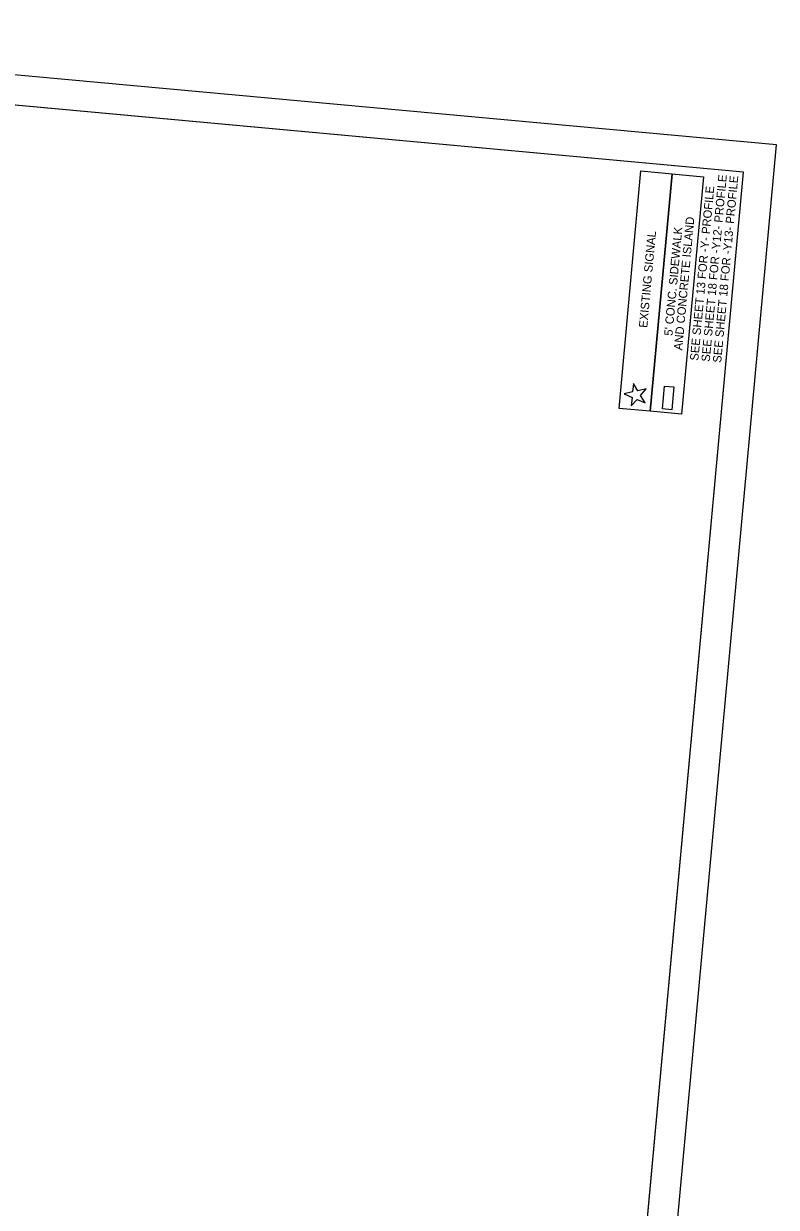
# Model space of a CAD drawing. Extents: x 2012234 to 2013485, y 445879 to 447846.
# Drawn here: x 2012860 to 2013485, y 446862 to 447846 of the extents above; entities that cross this region are included whole.
import ezdxf

# ---------------------------------------------------------------- set-up
doc = ezdxf.new("R2010")
doc.units = 0
for name, color, linetype in [('Old_Level_1', 7, 'Continuous'), ('Prop DSN Text', 7, 'Continuous'), ('Prop RDY Traffic Signal CELL', 7, 'Continuous'), ('Prop Shade Medium', 7, 'Continuous'), ('Sheet Clip Boundary CELL', 7, 'Continuous'), ('Sheet Plan And Profile CELL', 7, 'Continuous'), ('Sheet Plot Border Outside CELL', 7, 'Continuous')]:
    doc.layers.add(name, color=color, linetype=linetype)

msp = doc.modelspace()

# ---------------------------------------------------------------- linework, layer by layer
at = {"layer": 'Old_Level_1'}
for points in [[(2013354.62, 447526.24), (2013372.77, 447723.6), (2013398.72, 447721.22), (2013380.57, 447523.86)], [(2013380.57, 447523.86), (2013398.72, 447721.22), (2013424.67, 447718.83), (2013406.52, 447521.47)]]:
    msp.add_lwpolyline(points, close=True, dxfattribs=at)
at = {"layer": 'Prop RDY Traffic Signal CELL'}
msp.add_lwpolyline([(2013365.48, 447535.48), (2013364.82, 447528.31), (2013369.57, 447533.73), (2013376.21, 447530.88), (2013372.51, 447537.09), (2013377.27, 447542.51), (2013370.23, 447540.92), (2013366.54, 447547.12), (2013365.88, 447539.93), (2013358.84, 447538.34), (2013365.48, 447535.48)], dxfattribs=at)
at = {"layer": 'Prop Shade Medium'}
msp.add_lwpolyline([(2013390.77, 447525.92), (2013392.51, 447544.89), (2013400.1, 447544.19), (2013398.36, 447525.22)], close=True, dxfattribs=at)
at = {"layer": 'Sheet Clip Boundary CELL'}
msp.add_lwpolyline([(2012286.31, 446445.78), (2012511.43, 446429.21), (2012750.66, 446410.08), (2013333.05, 446362.08), (2013458.14, 447722.64), (2012593.82, 447802.11), (2012575.5, 447602.9), (2012460.65, 447613.46), (2012442.34, 447414.28), (2012375.93, 447420.39)], close=True, dxfattribs=at)
at = {"layer": 'Sheet Plan And Profile CELL'}
msp.add_lwpolyline([(2012412.56, 447818.78), (2012275.22, 446325.08), (2013320.81, 446228.94), (2013458.14, 447722.64)], close=True, dxfattribs=at)
at = {"layer": 'Sheet Plot Border Outside CELL'}
msp.add_lwpolyline([(2013329.68, 446052.39), (2013485.33, 447745.24), (2012389.95, 447845.96), (2012234.3, 446153.1)], close=True, dxfattribs=at)

# ---------------------------------------------------------------- texts
at = {"layer": 'Prop DSN Text'}
for s, p in [('SEE SHEET 18 FOR -Y12- PROFILE', (2013429.96, 447564.85)), ('SEE SHEET 18 FOR -Y13- PROFILE', (2013439.46, 447563.98)), ('SEE SHEET 13 FOR -Y- PROFILE', (2013420.46, 447565.72)), ("5' CONC. SIDEWALK", (2013398.98, 447586.39)), ('AND CONCRETE ISLAND', (2013407.09, 447574.38)), ('EXISTING SIGNAL', (2013378.02, 447593.02))]:
    msp.add_text(s, height=7, rotation=84.74666, dxfattribs=at).set_placement(p)

doc.saveas('drawing.dxf')
